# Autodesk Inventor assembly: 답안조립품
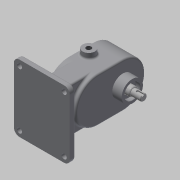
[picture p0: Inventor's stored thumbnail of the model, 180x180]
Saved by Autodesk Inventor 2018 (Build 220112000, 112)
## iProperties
Created: 2020-09
Part Number: 답안조립품
Material: 일반
Document SubType Name: Assembly
Designer: home
Author: home
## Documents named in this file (7)
- C:\Users\home\Desktop\700906V1031\답안조립품.iam
- C:\Users\home\Desktop\700906V1031\본체.ipt
- C:\Users\home\Desktop\700906V1031\베어링부시.ipt
- C:\Users\home\Desktop\700906V1031\스퍼기어.ipt
- C:\Users\home\Desktop\700906V1031\서브축.ipt
- C:\Users\home\Desktop\700906V1031\메인축.ipt
- C:\Users\home\Desktop\700906V1031\키 6 x 6 x 18.ipt
